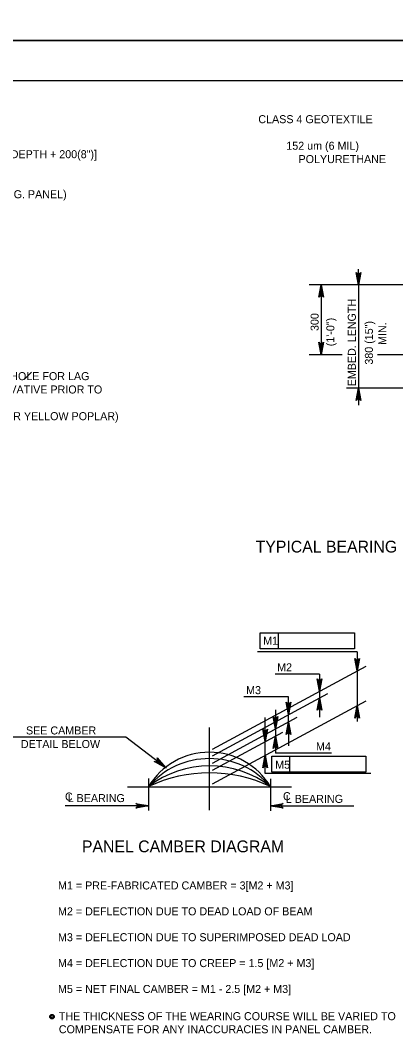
# Model space of a CAD drawing. Extents: x 638268 to 640277, y 295465 to 298435.
# Drawn here: x 639548.8 to 639689.3, y 296279.1 to 296661 of the extents above; entities that cross this region are included whole.
import ezdxf

# ---------------------------------------------------------------- set-up
doc = ezdxf.new("R2010")
doc.units = 0
for name, color, linetype in [('2', 7, 'Continuous'), ('3', 7, 'Continuous'), ('4', 7, 'Continuous'), ('5', 7, 'Continuous'), ('PLT-BNDY', 7, 'Continuous')]:
    doc.layers.add(name, color=color, linetype=linetype)

msp = doc.modelspace()

# ---------------------------------------------------------------- linework, layer by layer
at = {"layer": '2'}
for p, q in [((639316.46, 296638.46), (640102.46, 296638.46)), ((639588.93, 296373.85), (639650.24, 296373.85))]:
    msp.add_line(p, q, dxfattribs=at)
at = {"layer": '3'}
for p, q in [((639675.32, 296561.86), (639675.32, 296567.76)), ((639690.55, 296561.86), (639656.94, 296561.86)), ((639661.44, 296561.86), (639661.44, 296535.7)), ((639701.21, 296561.86), (639670.9, 296561.86)), ((639675.32, 296561.86), (639675.32, 296523.21)), ((639669.23, 296535.7), (639656.94, 296535.7)), ((639699.67, 296535.7), (639682.49, 296535.7)), ((639550.23, 296526.4), (639552.94, 296529.11)), ((639717.24, 296523.21), (639670.9, 296523.21)), ((639675.32, 296523.21), (639675.32, 296517.31)), ((639675.32, 296517.31), (639675.32, 296516.76))]:
    msp.add_line(p, q, dxfattribs=at)
for points in [[(639675.32, 296561.86), (639674.45, 296566.52), (639674.7, 296566.16), (639675.01, 296565.98), (639675.32, 296565.92), (639675.64, 296565.98), (639675.95, 296566.16), (639676.2, 296566.52), (639675.32, 296561.86), (639675.95, 296566.16), (639675.64, 296565.98), (639675.32, 296561.86), (639675.32, 296565.92), (639675.01, 296565.98), (639675.32, 296561.86), (639674.7, 296566.16)], [(639661.44, 296561.86), (639662.31, 296557.2), (639662.06, 296557.56), (639661.75, 296557.74), (639661.44, 296557.8), (639661.12, 296557.74), (639660.81, 296557.56), (639660.56, 296557.2), (639661.44, 296561.86), (639660.81, 296557.56), (639661.12, 296557.74), (639661.44, 296561.86), (639661.44, 296557.8), (639661.75, 296557.74), (639661.44, 296561.86), (639662.06, 296557.56)], [(639661.44, 296535.7), (639660.56, 296540.36), (639660.81, 296540), (639661.12, 296539.81), (639661.44, 296539.76), (639661.75, 296539.81), (639662.06, 296540), (639662.31, 296540.36), (639661.44, 296535.7), (639662.06, 296540), (639661.75, 296539.81), (639661.44, 296535.7), (639661.44, 296539.76), (639661.12, 296539.81), (639661.44, 296535.7), (639660.81, 296540)], [(639675.32, 296523.21), (639676.2, 296518.55), (639675.95, 296518.91), (639675.64, 296519.1), (639675.32, 296519.15), (639675.01, 296519.1), (639674.7, 296518.91), (639674.45, 296518.55), (639675.32, 296523.21), (639674.7, 296518.91), (639675.01, 296519.1), (639675.32, 296523.21), (639675.32, 296519.15), (639675.64, 296519.1), (639675.32, 296523.21), (639675.95, 296518.91)]]:
    msp.add_lwpolyline(points, dxfattribs=at)
for points in [[(639674.83, 296564.81), (639675.82, 296564.81), (639675.32, 296561.86)], [(639660.94, 296558.86), (639661.94, 296558.86), (639661.44, 296561.86)], [(639660.94, 296538.7), (639661.94, 296538.7), (639661.44, 296535.7)], [(639674.83, 296520.26), (639675.82, 296520.26), (639675.32, 296523.21)]]:
    msp.add_lwpolyline(points, close=True, dxfattribs=at)
at = {"layer": '4'}
for centre, radius, start, end in [((639619.58, 296360.04), 26.73, 31.1159, 148.8841), ((639619.58, 296354.27), 30.12, 40.5509, 139.4492), ((639619.58, 296343.95), 37.66, 52.5765, 127.4235), ((639619.58, 296325.77), 53.26, 64.5513, 115.4487)]:
    msp.add_arc(centre, radius, start, end, dxfattribs=at)
at = {"layer": '5'}
for p, q in [((639638.59, 296431.46), (639645.44, 296431.46)), ((639638.59, 296425.56), (639638.59, 296431.46)), ((639645.44, 296425.56), (639645.44, 296431.46)), ((639645.44, 296431.46), (639673.89, 296431.46)), ((639673.89, 296431.46), (639673.89, 296425.56)), ((639673.89, 296425.56), (639638.59, 296425.56)), ((639674.86, 296424.34), (639637.51, 296424.34)), ((639674.86, 296424.34), (639674.86, 296398.25)), ((639620.65, 296387.94), (639678.25, 296419.06)), ((639660.8, 296416.04), (639644.17, 296416.04)), ((639660.8, 296416.04), (639660.8, 296399.96)), ((639620.65, 296385.46), (639663.86, 296408.8)), ((639620.65, 296374.92), (639678.25, 296406.04)), ((639649.16, 296407.49), (639632.48, 296407.49)), ((639649.16, 296396.88), (639649.16, 296407.49)), ((639644.27, 296402.61), (639644.27, 296386.41)), ((639620.65, 296382.67), (639652.45, 296399.85)), ((639640.47, 296378.81), (639640.47, 296399.75)), ((639619.58, 296365.11), (639619.58, 296396.06)), ((639620.65, 296380.09), (639646.98, 296394.31)), ((639649.16, 296396.88), (639649.16, 296389.22)), ((639588.32, 296392.38), (639545.62, 296392.38)), ((639603.12, 296381.1), (639588.32, 296392.38)), ((639665.28, 296386.41), (639644.27, 296386.41)), ((639642.87, 296385.24), (639649.71, 296385.24)), ((639642.87, 296379.33), (639642.87, 296385.24)), ((639649.71, 296379.33), (639649.71, 296385.24)), ((639649.71, 296385.24), (639678.17, 296385.24)), ((639678.17, 296385.24), (639678.17, 296379.33)), ((639679.97, 296378.81), (639640.47, 296378.81)), ((639678.17, 296379.33), (639642.87, 296379.33)), ((639596.7, 296376.9), (639596.7, 296364.98)), ((639642.47, 296376.77), (639642.47, 296364.84)), ((639596.7, 296366.72), (639565.56, 296366.72)), ((639642.47, 296366.72), (639673.61, 296366.72))]:
    msp.add_line(p, q, dxfattribs=at)
for points in [[(639674.86, 296417.23), (639673.99, 296421.89), (639674.24, 296421.53), (639674.55, 296421.35), (639674.86, 296421.29), (639675.18, 296421.35), (639675.49, 296421.53), (639675.74, 296421.89), (639674.86, 296417.23), (639675.49, 296421.53), (639675.18, 296421.35), (639674.86, 296417.23), (639674.86, 296421.29), (639674.55, 296421.35), (639674.86, 296417.23), (639674.24, 296421.53)], [(639660.8, 296409.63), (639659.92, 296414.29), (639660.17, 296413.93), (639660.48, 296413.75), (639660.8, 296413.69), (639661.11, 296413.75), (639661.42, 296413.93), (639661.67, 296414.29), (639660.8, 296409.63), (639661.42, 296413.93), (639661.11, 296413.75), (639660.8, 296409.63), (639660.8, 296413.69), (639660.48, 296413.75), (639660.8, 296409.63), (639660.17, 296413.93)], [(639649.16, 296400.86), (639648.29, 296405.52), (639648.54, 296405.16), (639648.85, 296404.98), (639649.16, 296404.92), (639649.47, 296404.98), (639649.79, 296405.16), (639650.03, 296405.52), (639649.16, 296400.86), (639649.79, 296405.16), (639649.47, 296404.98), (639649.16, 296400.86), (639649.16, 296404.92), (639648.85, 296404.98), (639649.16, 296400.86), (639648.54, 296405.16)], [(639660.8, 296407.15), (639661.67, 296402.48), (639661.42, 296402.85), (639661.11, 296403.03), (639660.8, 296403.08), (639660.48, 296403.03), (639660.17, 296402.85), (639659.92, 296402.48), (639660.8, 296407.15), (639660.17, 296402.85), (639660.48, 296403.03), (639660.8, 296407.15), (639660.8, 296403.08), (639661.11, 296403.03), (639660.8, 296407.15), (639661.42, 296402.85)], [(639674.86, 296404.21), (639675.74, 296399.55), (639675.49, 296399.91), (639675.18, 296400.09), (639674.86, 296400.15), (639674.55, 296400.09), (639674.24, 296399.91), (639673.99, 296399.55), (639674.86, 296404.21), (639674.24, 296399.91), (639674.55, 296400.09), (639674.86, 296404.21), (639674.86, 296400.15), (639675.18, 296400.09), (639674.86, 296404.21), (639675.49, 296399.91)], [(639644.27, 296395.43), (639643.39, 296400.09), (639643.64, 296399.73), (639643.95, 296399.55), (639644.27, 296399.49), (639644.58, 296399.55), (639644.89, 296399.73), (639645.14, 296400.09), (639644.27, 296395.43), (639644.89, 296399.73), (639644.58, 296399.55), (639644.27, 296395.43), (639644.27, 296399.49), (639643.95, 296399.55), (639644.27, 296395.43), (639643.64, 296399.73)], [(639649.16, 296398.07), (639650.03, 296393.41), (639649.79, 296393.77), (639649.47, 296393.96), (639649.16, 296394.01), (639648.85, 296393.96), (639648.54, 296393.77), (639648.29, 296393.41), (639649.16, 296398.07), (639648.54, 296393.77), (639648.85, 296393.96), (639649.16, 296398.07), (639649.16, 296394.01), (639649.47, 296393.96), (639649.16, 296398.07), (639649.79, 296393.77)], [(639640.47, 296390.79), (639639.59, 296395.45), (639639.84, 296395.1), (639640.15, 296394.91), (639640.47, 296394.86), (639640.78, 296394.91), (639641.09, 296395.1), (639641.34, 296395.45), (639640.47, 296390.79), (639641.09, 296395.1), (639640.78, 296394.91), (639640.47, 296390.79), (639640.47, 296394.86), (639640.15, 296394.91), (639640.47, 296390.79), (639639.84, 296395.1)], [(639644.27, 296392.85), (639645.14, 296388.19), (639644.89, 296388.55), (639644.58, 296388.73), (639644.27, 296388.78), (639643.95, 296388.73), (639643.64, 296388.55), (639643.39, 296388.19), (639644.27, 296392.85), (639643.64, 296388.55), (639643.95, 296388.73), (639644.27, 296392.85), (639644.27, 296388.78), (639644.58, 296388.73), (639644.27, 296392.85), (639644.89, 296388.55)], [(639603.12, 296381.1), (639598.88, 296383.23), (639599.32, 296383.21), (639599.65, 296383.34), (639599.89, 296383.56), (639600.03, 296383.84), (639600.07, 296384.2), (639599.94, 296384.62), (639603.12, 296381.1), (639600.07, 296384.2), (639600.03, 296383.84), (639603.12, 296381.1), (639599.89, 296383.56), (639599.65, 296383.34), (639603.12, 296381.1), (639599.32, 296383.21)], [(639640.47, 296385.63), (639641.34, 296380.97), (639641.09, 296381.32), (639640.78, 296381.51), (639640.47, 296381.56), (639640.15, 296381.51), (639639.84, 296381.32), (639639.59, 296380.97), (639640.47, 296385.63), (639639.84, 296381.32), (639640.15, 296381.51), (639640.47, 296385.63), (639640.47, 296381.56), (639640.78, 296381.51), (639640.47, 296385.63), (639641.09, 296381.32)], [(639596.7, 296366.72), (639592.04, 296365.85), (639592.4, 296366.09), (639592.58, 296366.41), (639592.64, 296366.72), (639592.58, 296367.03), (639592.4, 296367.34), (639592.04, 296367.59), (639596.7, 296366.72), (639592.4, 296367.34), (639592.58, 296367.03), (639596.7, 296366.72), (639592.64, 296366.72), (639592.58, 296366.41), (639596.7, 296366.72), (639592.4, 296366.09)], [(639642.47, 296366.72), (639647.13, 296367.59), (639646.77, 296367.34), (639646.58, 296367.03), (639646.53, 296366.72), (639646.58, 296366.41), (639646.77, 296366.09), (639647.13, 296365.85), (639642.47, 296366.72), (639646.77, 296366.09), (639646.58, 296366.41), (639642.47, 296366.72), (639646.53, 296366.72), (639646.58, 296367.03), (639642.47, 296366.72), (639646.77, 296367.34)]]:
    msp.add_lwpolyline(points, dxfattribs=at)
for points in [[(639660.3, 296404.19), (639661.29, 296404.19), (639660.8, 296407.15)], [(639601.29, 296383.12), (639600.68, 296382.33), (639603.37, 296380.9)]]:
    msp.add_lwpolyline(points, close=True, dxfattribs=at)
for radius in [0.833, 0.417]:
    msp.add_circle((639560.62, 296287.69), radius, dxfattribs=at)
at = {"layer": 'PLT-BNDY'}
for points in [[(639276.46, 297247.46), (640117.46, 297247.46), (640117.46, 296653.46), (639276.46, 296653.46)], [(639276.46, 296653.46), (640117.46, 296653.46), (640117.46, 296059.46), (639276.46, 296059.46)]]:
    msp.add_lwpolyline(points, close=True, dxfattribs=at)

# ---------------------------------------------------------------- texts
at = {"layer": '2'}
msp.add_text('TYPICAL BEARING DETAIL - CONCRETE ABUTMENT', height=4.4292, dxfattribs=at).set_placement((639636.85, 296461.58))
at = {"layer": '3'}
for s, p in [('CLASS 4 GEOTEXTILE', (639637.87, 296622.44)), ('152 um (6 MIL)', (639648.34, 296612.49)), ('19.1(3/4") 0 LAG SCREW [LENGTH = PANEL DEPTH + 200(8")]', (639461.81, 296609.32)), ('POLYURETHANE', (639652.92, 296607.49)), ('(RECESS 85 (3 3/8") O x 25 (1") DEEP IN LONG. PANEL)', (639461.81, 296594.32)), ('FIELD DRILL 14.3 (9/16") 0 PILOT HOLE FOR LAG', (639482.02, 296526.17)), ('SCREW AND FILL WITH PRESERVATIVE PRIOR TO', (639482.02, 296521.17)), ('(USE 12.7 (1/2") 0 PILOT HOLE FOR YELLOW POPLAR)', (639482.02, 296511.17))]:
    msp.add_text(s, height=3, dxfattribs=at).set_placement(p)
for s, p in [('EMBED. LENGTH', (639674.37, 296523.86)), ('300', (639660.44, 296544.58)), ('(1\'-0")', (639666.33, 296538.87)), ('380 (15")', (639680.76, 296531.98)), ('MIN.', (639685.76, 296539.36))]:
    msp.add_text(s, height=3, rotation=90, dxfattribs=at).set_placement(p)
at = {"layer": '5'}
for s, height, p in [('M1', 3, (639639.68, 296427.04)), ('M2', 3, (639644.91, 296417.08)), ('M3', 3, (639633.29, 296408.52)), ('SEE CAMBER', 3, (639550.87, 296393.43)), ('DETAIL BELOW', 3, (639548.97, 296388.33)), ('M4', 3, (639659.45, 296387.44)), ('M5', 3, (639644.18, 296380.58)), ('C', 3, (639565.46, 296368.65)), ('L BEARING', 3, (639566.48, 296368.08)), ('C', 3, (639647.08, 296368.79)), ('L BEARING', 3, (639648.15, 296367.79)), ('PANEL CAMBER DIAGRAM', 4.4292, (639571.82, 296349.27)), ('M1 = PRE-FABRICATED CAMBER = 3[M2 + M3]', 3, (639562.86, 296335.35)), ('M2 = DEFLECTION DUE TO DEAD LOAD OF BEAM', 3, (639562.86, 296325.65)), ('M3 = DEFLECTION DUE TO SUPERIMPOSED DEAD LOAD', 3, (639562.86, 296315.96)), ('M4 = DEFLECTION DUE TO CREEP = 1.5 [M2 + M3]', 3, (639562.86, 296306.26)), ('M5 = NET FINAL CAMBER = M1 - 2.5 [M2 + M3]', 3, (639562.86, 296296.57)), (' THE THICKNESS OF THE WEARING COURSE WILL BE VARIED TO', 3, (639562.06, 296286.37)), (' COMPENSATE FOR ANY INACCURACIES IN PANEL CAMBER.', 3, (639562.06, 296281.47))]:
    msp.add_text(s, height=height, dxfattribs=at).set_placement(p)

doc.saveas('drawing.dxf')
